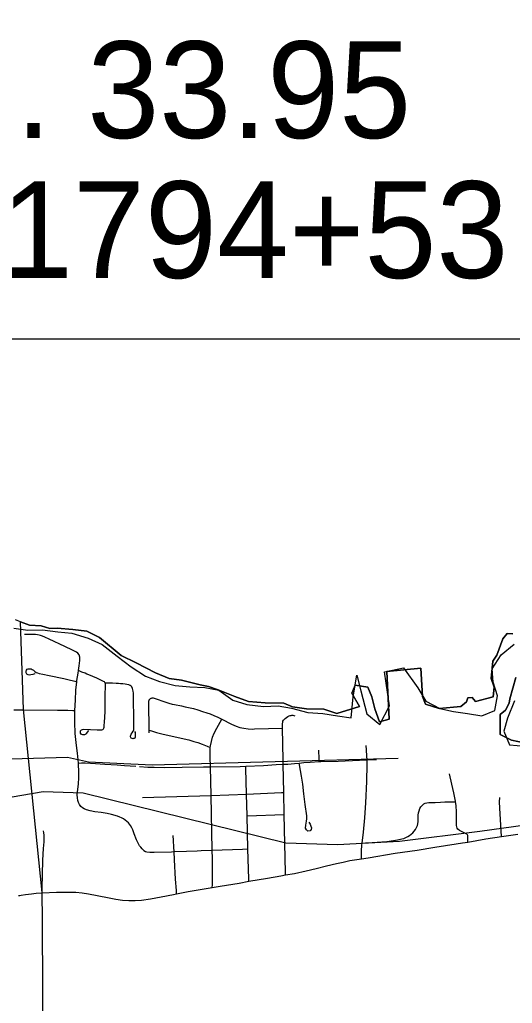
# Model space of a CAD drawing. Extents: x -12 to 34, y 0 to 22.
# Drawn here: x 7.187 to 7.899, y 18.102 to 19.526 of the extents above; entities that cross this region are included whole.
import ezdxf

# ---------------------------------------------------------------- set-up
doc = ezdxf.new("R2010")
doc.units = 0
for name, color, linetype in [('GM_X_Adjacent_County', 7, 'Continuous'), ('GM_X_Airport_Location_Class_2', 7, 'Continuous'), ('GM_X_Corporation', 7, 'Continuous'), ('GM_X_Major_Lake', 7, 'Continuous'), ('GM_X_Major_River', 7, 'Continuous'), ('GM_X_Minor_River', 7, 'Continuous'), ('GM_X_State_Location', 7, 'Continuous'), ('GM_X_Township', 7, 'Continuous')]:
    doc.layers.add(name, color=color, linetype=linetype)

msp = doc.modelspace()

# ---------------------------------------------------------------- linework, layer by layer
at = {"layer": 'GM_X_Adjacent_County'}
msp.add_lwpolyline([(6.6266, 19.8024), (8.3735, 19.8024), (8.3735, 19.0635), (6.6266, 19.0635)], close=True, dxfattribs=at)
at = {"layer": 'GM_X_Airport_Location_Class_2'}
for points in [[(7.9003, 18.6372), (7.8917, 18.6377), (7.8855, 18.6297), (7.8772, 18.6063), (7.8713, 18.5977), (7.8686, 18.5722), (7.8732, 18.5601), (7.8717, 18.5459), (7.846, 18.5389), (7.8412, 18.5448), (7.8348, 18.5445), (7.8331, 18.5386), (7.8251, 18.5321), (7.7935, 18.5292), (7.7738, 18.5354), (7.7692, 18.5466), (7.7668, 18.5872), (7.7177, 18.5824), (7.7211, 18.5136), (7.7071, 18.5096), (7.7007, 18.5286), (7.6959, 18.5458), (7.6905, 18.5598), (7.6722, 18.5628), (7.6674, 18.5512), (7.6781, 18.5321), (7.6454, 18.5219), (7.6266, 18.5281), (7.6016, 18.5286), (7.5814, 18.5316), (7.5688, 18.5367), (7.5419, 18.5372), (7.5177, 18.5391), (7.4979, 18.5466), (7.4738, 18.5558), (7.46, 18.5609), (7.4476, 18.5633), (7.4208, 18.5698), (7.403, 18.5722), (7.3829, 18.5805), (7.3552, 18.595), (7.3337, 18.6058), (7.302, 18.6315), (7.284, 18.6407), (7.2633, 18.6434), (7.2408, 18.645), (7.2303, 18.6447), (7.2177, 18.6487), (7.201, 18.6498), (7.1879, 18.6546), (7.1806, 18.6573)], [(7.9003, 18.6372), (7.8917, 18.6377), (7.8855, 18.6297), (7.8772, 18.6063), (7.8713, 18.5977), (7.8686, 18.5722), (7.8732, 18.5601), (7.8717, 18.5459), (7.846, 18.5389), (7.8412, 18.5448), (7.8348, 18.5445), (7.8331, 18.5386), (7.8251, 18.5321), (7.7935, 18.5292), (7.7738, 18.5354), (7.7692, 18.5466), (7.7668, 18.5872), (7.7177, 18.5824), (7.7211, 18.5136), (7.7071, 18.5096), (7.7007, 18.5286), (7.6959, 18.5458), (7.6905, 18.5598), (7.6722, 18.5628), (7.6674, 18.5512), (7.6781, 18.5321), (7.6454, 18.5219), (7.6266, 18.5281), (7.6016, 18.5286), (7.5814, 18.5316), (7.5688, 18.5367), (7.5419, 18.5372), (7.5177, 18.5391), (7.4979, 18.5466), (7.4738, 18.5558), (7.46, 18.5609), (7.4476, 18.5633), (7.4208, 18.5698), (7.403, 18.5722), (7.3829, 18.5805), (7.3552, 18.595), (7.3337, 18.6058), (7.302, 18.6315), (7.284, 18.6407), (7.2633, 18.6434), (7.2408, 18.645), (7.2303, 18.6447), (7.2177, 18.6487), (7.201, 18.6498), (7.1879, 18.6546), (7.1806, 18.6573)], [(7.2233, 17.4111), (7.2195, 18.2227), (7.219, 18.2628), (7.192, 18.5278), (7.1879, 18.6546), (7.201, 18.6498), (7.2177, 18.6487), (7.2303, 18.6447), (7.2408, 18.645), (7.2633, 18.6434), (7.284, 18.6407), (7.302, 18.6315), (7.3337, 18.6058), (7.3552, 18.595), (7.3829, 18.5805), (7.403, 18.5722), (7.4208, 18.5698), (7.4476, 18.5633), (7.46, 18.5609), (7.4738, 18.5558), (7.4979, 18.5466), (7.5177, 18.5391), (7.5419, 18.5372), (7.5688, 18.5367), (7.5814, 18.5316), (7.6016, 18.5286), (7.6266, 18.5281), (7.6454, 18.5219), (7.6781, 18.5321), (7.6674, 18.5512), (7.6722, 18.5628), (7.6905, 18.5598), (7.6959, 18.5458), (7.7007, 18.5286), (7.7071, 18.5096), (7.7211, 18.5136), (7.7177, 18.5824), (7.7668, 18.5872), (7.7692, 18.5466), (7.7738, 18.5354), (7.7935, 18.5292), (7.8251, 18.5321), (7.8331, 18.5386), (7.8348, 18.5445), (7.8412, 18.5448), (7.846, 18.5389), (7.8717, 18.5459), (7.8732, 18.5601), (7.8686, 18.5722), (7.8713, 18.5977), (7.8772, 18.6063), (7.8855, 18.6297), (7.8917, 18.6377), (7.9003, 18.6372)], [(7.9167, 18.4795), (7.8984, 18.4832), (7.882, 18.4913), (7.8818, 18.5203), (7.8893, 18.5265), (7.8949, 18.5367), (7.8957, 18.5429), (7.9043, 18.5738)], [(7.9043, 18.5738), (7.8957, 18.5429), (7.8949, 18.5367), (7.8893, 18.5265), (7.8818, 18.5203), (7.882, 18.4913), (7.8984, 18.4832), (7.9167, 18.4795)], [(7.9167, 18.4795), (7.8984, 18.4832), (7.882, 18.4913), (7.8818, 18.5203), (7.8893, 18.5265), (7.8949, 18.5367), (7.8957, 18.5429), (7.9043, 18.5738)]]:
    msp.add_lwpolyline(points, dxfattribs=at)
at = {"layer": 'GM_X_Corporation'}
for points in [[(4.2152, 16.8961), (4.3122, 16.9647), (4.7469, 17.316), (5.0381, 17.5535), (5.1871, 17.6698), (5.6595, 18.0409), (6.0545, 18.3551), (6.0978, 18.3867), (6.1312, 18.4021), (6.1695, 18.4095), (6.5535, 18.4423), (6.6901, 18.4479), (6.8503, 18.4485), (6.9294, 18.4522), (7.1075, 18.4541), (7.2559, 18.4584), (7.2861, 18.4516), (7.3783, 18.4473), (7.7344, 18.4572)], [(5.8151, 17.1077), (6.2198, 17.2736), (6.4243, 17.354), (6.5061, 17.4016), (6.5567, 17.4596), (6.585, 17.5147), (6.6051, 17.5675), (6.6162, 17.6256), (6.62, 17.674), (6.6177, 18.0624), (6.6371, 18.1271), (6.6557, 18.1606), (6.7018, 18.1993), (6.7606, 18.2254), (7.0425, 18.3601), (7.0932, 18.3811), (7.1588, 18.3984), (7.2206, 18.4089), (7.2787, 18.4071), (7.5718, 18.3347), (7.6466, 18.3322), (7.7363, 18.3372), (7.8525, 18.3514), (8.033, 18.3768)]]:
    msp.add_lwpolyline(points, dxfattribs=at)
at = {"layer": 'GM_X_Major_Lake'}
for points in [[(7.4653, 18.2699), (7.4766, 18.2718), (7.5042, 18.2765), (7.5181, 18.279), (7.5453, 18.2837), (7.5644, 18.2871), (7.5714, 18.2883), (7.5843, 18.2905), (7.6011, 18.294), (7.6156, 18.2974), (7.6307, 18.3012), (7.6448, 18.3047), (7.6545, 18.3069), (7.6645, 18.3089), (7.6814, 18.3116), (7.6909, 18.3131), (7.7298, 18.3196), (7.7617, 18.324), (7.7875, 18.3282), (7.8182, 18.333), (7.8273, 18.3346), (7.8352, 18.3358), (7.8613, 18.3403), (7.8838, 18.3438), (7.9073, 18.3473)], [(7.1851, 18.2582), (7.1868, 18.2585), (7.1889, 18.2589), (7.195, 18.2599), (7.2035, 18.2609)], [(7.2035, 18.2609), (7.2105, 18.2616), (7.2192, 18.2622), (7.2399, 18.2633), (7.2554, 18.2635), (7.2678, 18.2631), (7.277, 18.2623), (7.2862, 18.261), (7.3136, 18.2554), (7.3259, 18.2533), (7.3352, 18.2517), (7.3445, 18.251), (7.3538, 18.251), (7.3629, 18.2519), (7.3757, 18.2538), (7.3911, 18.2563), (7.4093, 18.2599), (7.4137, 18.2608), (7.4306, 18.264), (7.4653, 18.2699)]]:
    msp.add_lwpolyline(points, dxfattribs=at)
at = {"layer": 'GM_X_Major_River'}
msp.add_line((7.1783, 18.5271), (7.1922, 18.5272), dxfattribs=at)
at = {"layer": 'GM_X_Minor_River'}
for points in [[(7.1781, 18.645), (7.1986, 18.6423), (7.2196, 18.6427), (7.242, 18.6397), (7.2621, 18.6382), (7.2857, 18.6309), (7.3059, 18.6214), (7.3279, 18.6047), (7.3477, 18.5895), (7.3686, 18.5758), (7.3888, 18.5679), (7.4116, 18.5622), (7.4329, 18.5603), (7.4546, 18.5595), (7.4747, 18.5557), (7.4949, 18.5413), (7.5154, 18.5348), (7.5394, 18.5318), (7.5606, 18.5329), (7.58, 18.5295), (7.6036, 18.5234), (7.6253, 18.5219), (7.6466, 18.5185), (7.666, 18.5155), (7.669, 18.5459), (7.6743, 18.5774), (7.6804, 18.5546), (7.6888, 18.5215), (7.7078, 18.506), (7.7215, 18.5329), (7.7146, 18.582), (7.742, 18.588), (7.7629, 18.5588), (7.7743, 18.5394), (7.7945, 18.5292), (7.8143, 18.5246), (7.8344, 18.5216), (7.8553, 18.5185), (7.8743, 18.5261), (7.8781, 18.5474), (7.8717, 18.5672), (7.8701, 18.5865), (7.8831, 18.6067), (7.9021, 18.6223)], [(7.1781, 18.645), (7.1986, 18.6423), (7.2196, 18.6427), (7.242, 18.6397), (7.2621, 18.6382), (7.2857, 18.6309), (7.3059, 18.6214), (7.3279, 18.6047), (7.3477, 18.5895), (7.3686, 18.5758), (7.3888, 18.5679), (7.4116, 18.5622), (7.4329, 18.5603), (7.4546, 18.5595), (7.4747, 18.5557), (7.4949, 18.5413), (7.5154, 18.5348), (7.5394, 18.5318), (7.5606, 18.5329), (7.58, 18.5295), (7.6036, 18.5234), (7.6253, 18.5219), (7.6466, 18.5185), (7.666, 18.5155), (7.669, 18.5459), (7.6743, 18.5774), (7.6804, 18.5546), (7.6888, 18.5215), (7.7078, 18.506), (7.7215, 18.5329), (7.7146, 18.582), (7.742, 18.588), (7.7629, 18.5588), (7.7743, 18.5394), (7.7945, 18.5292), (7.8143, 18.5246), (7.8344, 18.5216), (7.8553, 18.5185), (7.8743, 18.5261), (7.8781, 18.5474), (7.8717, 18.5672), (7.8701, 18.5865), (7.8831, 18.6067), (7.9021, 18.6223)], [(7.9025, 18.5402), (7.8926, 18.5151), (7.8869, 18.4961), (7.8953, 18.4763), (7.9173, 18.4745)], [(7.9025, 18.5402), (7.8926, 18.5151), (7.8869, 18.4961), (7.8953, 18.4763), (7.9173, 18.4745)]]:
    msp.add_lwpolyline(points, dxfattribs=at)
at = {"layer": 'GM_X_State_Location'}
msp.add_line((7.5157, 18.3738), (7.5695, 18.3755), dxfattribs=at)
for points in [[(7.3665, 18.3234), (7.3639, 18.3259), (7.3618, 18.3283), (7.3599, 18.3305), (7.3585, 18.333), (7.3569, 18.3363), (7.3556, 18.3392), (7.3525, 18.3477), (7.3513, 18.3507), (7.3503, 18.3535), (7.349, 18.3564), (7.3471, 18.3597), (7.3456, 18.3618), (7.3439, 18.3637), (7.3417, 18.3657), (7.3393, 18.3676), (7.3367, 18.3692), (7.334, 18.3707), (7.3313, 18.3719), (7.3284, 18.373), (7.3195, 18.3756), (7.3131, 18.377), (7.3046, 18.3784), (7.2956, 18.3797), (7.2885, 18.381), (7.2834, 18.3824), (7.2801, 18.3839), (7.2777, 18.3853), (7.2753, 18.3873), (7.2731, 18.3903), (7.2715, 18.3932), (7.2707, 18.3961), (7.2702, 18.3996), (7.27, 18.4043), (7.2715, 18.4199), (7.2723, 18.4288), (7.2723, 18.4376), (7.2716, 18.4487), (7.2715, 18.4498), (7.2701, 18.4642), (7.2689, 18.4754), (7.2671, 18.4927), (7.2663, 18.5092), (7.2665, 18.5249), (7.2665, 18.526), (7.2673, 18.5412), (7.2681, 18.5555), (7.2693, 18.5676), (7.2695, 18.5694), (7.2711, 18.58), (7.2716, 18.5838), (7.2725, 18.5907), (7.2735, 18.5983), (7.2739, 18.6035), (7.2729, 18.6068), (7.271, 18.6089), (7.2687, 18.6106), (7.2632, 18.6133), (7.2518, 18.6186), (7.2293, 18.6292), (7.2231, 18.632), (7.2195, 18.6336), (7.2169, 18.6346), (7.2147, 18.6353), (7.2124, 18.6358), (7.2096, 18.6361), (7.206, 18.6362), (7.1998, 18.6362), (7.1938, 18.6359)], [(7.2088, 18.5792), (7.2055, 18.578), (7.203, 18.5775), (7.2007, 18.5774), (7.199, 18.5777), (7.1979, 18.5781), (7.1971, 18.5788), (7.1964, 18.5797), (7.1961, 18.5807), (7.196, 18.5819), (7.196, 18.583), (7.1965, 18.5846), (7.1975, 18.5858), (7.1987, 18.5863), (7.2002, 18.5866), (7.2018, 18.5865), (7.2034, 18.5862), (7.2047, 18.5855), (7.2064, 18.5843), (7.2085, 18.5826), (7.2105, 18.5813), (7.2125, 18.5804), (7.2147, 18.5797), (7.22, 18.5787), (7.2292, 18.5769), (7.2505, 18.5723), (7.2565, 18.5709), (7.2663, 18.5684), (7.2693, 18.5676)], [(7.2863, 18.4973), (7.283, 18.4929), (7.2822, 18.492), (7.2815, 18.4913), (7.2805, 18.4909), (7.2793, 18.4907), (7.278, 18.4908), (7.2765, 18.4912), (7.2756, 18.4918), (7.2748, 18.4931), (7.2745, 18.4942), (7.2745, 18.4952), (7.2748, 18.4965), (7.2753, 18.4974), (7.2763, 18.4983), (7.2777, 18.4987), (7.2795, 18.499), (7.2988, 18.498), (7.3041, 18.498), (7.3057, 18.4981), (7.3068, 18.4985), (7.3075, 18.4989), (7.3081, 18.4996), (7.3085, 18.5004), (7.3088, 18.5019), (7.3091, 18.5047), (7.3094, 18.5088), (7.3101, 18.5245), (7.3105, 18.5472), (7.311, 18.5626), (7.3109, 18.5639), (7.3107, 18.5649), (7.3104, 18.5657), (7.3098, 18.5668), (7.3092, 18.5675), (7.308, 18.5681), (7.2982, 18.5728), (7.2924, 18.5752), (7.2867, 18.5775), (7.284, 18.5787), (7.2814, 18.5799), (7.2765, 18.5818), (7.2716, 18.5838)], [(7.3528, 18.4958), (7.3535, 18.4942), (7.3538, 18.4925), (7.3539, 18.4909), (7.3539, 18.4894), (7.3539, 18.4882), (7.3536, 18.4872), (7.3534, 18.4866), (7.353, 18.486), (7.3524, 18.4856), (7.3515, 18.4855), (7.3506, 18.4853), (7.3492, 18.4856), (7.3481, 18.4861), (7.3475, 18.4869), (7.3472, 18.488), (7.3472, 18.4892), (7.3475, 18.4904), (7.348, 18.4917), (7.3495, 18.494), (7.351, 18.496), (7.3514, 18.4969), (7.3518, 18.498), (7.3519, 18.4993), (7.352, 18.5047), (7.3519, 18.5111), (7.3516, 18.5206), (7.3515, 18.5361), (7.3514, 18.5435), (7.3514, 18.5477), (7.3513, 18.5513), (7.351, 18.5542), (7.3505, 18.5561), (7.3499, 18.5579), (7.3487, 18.5602), (7.3477, 18.5612), (7.3463, 18.5623), (7.3446, 18.5632), (7.3419, 18.5639), (7.3391, 18.5642), (7.336, 18.5645), (7.3326, 18.5648), (7.3297, 18.565), (7.3261, 18.5652), (7.3208, 18.5655), (7.3139, 18.5657), (7.3104, 18.5657)], [(7.3741, 18.4938), (7.374, 18.4976), (7.3734, 18.5377), (7.3736, 18.5392), (7.3737, 18.5401), (7.3739, 18.5408), (7.3742, 18.5414), (7.3745, 18.542), (7.375, 18.5426), (7.3755, 18.5431), (7.376, 18.5435), (7.3767, 18.5438), (7.3773, 18.544), (7.3781, 18.5442), (7.3796, 18.5442), (7.3812, 18.5439), (7.3842, 18.543), (7.3954, 18.539), (7.4025, 18.5367), (7.4071, 18.5354), (7.4106, 18.5347), (7.4209, 18.5327), (7.426, 18.5316), (7.4381, 18.5289), (7.4444, 18.527), (7.4509, 18.5249), (7.4574, 18.5229), (7.4621, 18.5213), (7.4675, 18.5191), (7.4731, 18.5164), (7.4791, 18.5135), (7.493, 18.5063), (7.4997, 18.5035), (7.5052, 18.5017), (7.5109, 18.5004), (7.5171, 18.4997), (7.5233, 18.4993), (7.5266, 18.4994), (7.5667, 18.5004), (7.5669, 18.5049), (7.567, 18.5068), (7.5673, 18.5091), (7.5676, 18.5107), (7.5683, 18.512), (7.5692, 18.5131), (7.5705, 18.5143), (7.5728, 18.516), (7.5747, 18.5172), (7.5766, 18.5182), (7.5779, 18.5187), (7.5794, 18.5191), (7.5806, 18.5192), (7.5817, 18.5192), (7.5831, 18.519), (7.5845, 18.5184)], [(7.1922, 18.5272), (7.2414, 18.5266), (7.2564, 18.5264), (7.2633, 18.5261), (7.2665, 18.526)], [(7.4653, 18.2699), (7.4654, 18.2737), (7.4658, 18.2923), (7.4655, 18.312), (7.4653, 18.3241), (7.4636, 18.4031), (7.4625, 18.4447), (7.4621, 18.4587), (7.4621, 18.4679), (7.4624, 18.4725), (7.4628, 18.475), (7.4641, 18.4812), (7.4658, 18.4875), (7.468, 18.4931), (7.4718, 18.5006), (7.4767, 18.5093), (7.4791, 18.5135)], [(7.374, 18.4976), (7.3787, 18.496), (7.3846, 18.4943), (7.3944, 18.4921), (7.4313, 18.4835), (7.4387, 18.4815), (7.4444, 18.4796), (7.4507, 18.4772), (7.4577, 18.4745), (7.4624, 18.4725)], [(7.5714, 18.2883), (7.5713, 18.2919), (7.5695, 18.3755), (7.5688, 18.4075), (7.5679, 18.4483), (7.5677, 18.4546), (7.5667, 18.5004)], [(7.6814, 18.3116), (7.6814, 18.3158), (7.6814, 18.3231), (7.6817, 18.3314), (7.6821, 18.334), (7.6841, 18.3501), (7.6861, 18.3707), (7.6875, 18.3926), (7.6889, 18.4232), (7.6893, 18.4479), (7.6892, 18.4545), (7.6891, 18.4602), (7.6885, 18.4694), (7.6879, 18.4756)], [(7.6201, 18.4521), (7.6199, 18.4557), (7.6197, 18.4605), (7.6196, 18.4643), (7.6194, 18.4688)], [(7.2715, 18.4498), (7.2763, 18.4503), (7.2816, 18.4503), (7.2961, 18.4495), (7.3099, 18.4485), (7.3278, 18.4474), (7.3382, 18.4466), (7.3548, 18.4454)], [(7.36, 18.445), (7.3719, 18.4443), (7.3812, 18.444), (7.3967, 18.4437), (7.4216, 18.4439), (7.4526, 18.4445), (7.4625, 18.4447), (7.5057, 18.4453), (7.5137, 18.4457), (7.5394, 18.4467), (7.5579, 18.4478), (7.5679, 18.4483), (7.5747, 18.4486), (7.5844, 18.4494), (7.5911, 18.4501), (7.5979, 18.4508), (7.6071, 18.4514), (7.6201, 18.4521), (7.6225, 18.4522), (7.6474, 18.4528), (7.6784, 18.4541), (7.6892, 18.4545), (7.703, 18.455)], [(7.5181, 18.279), (7.518, 18.282), (7.5169, 18.3261), (7.5157, 18.3738), (7.5149, 18.405), (7.5138, 18.4424), (7.5137, 18.4457)], [(7.605, 18.3644), (7.6067, 18.3617), (7.608, 18.3589), (7.6088, 18.3564), (7.6085, 18.3537), (7.6067, 18.3519), (7.6037, 18.3517), (7.6014, 18.3533), (7.6003, 18.3559), (7.6006, 18.3604), (7.6018, 18.3662), (7.602, 18.3693), (7.6019, 18.3736), (7.5998, 18.3902), (7.5979, 18.4055), (7.5961, 18.4196), (7.5946, 18.431), (7.5916, 18.4476), (7.5911, 18.4501)], [(7.8174, 18.3939), (7.8173, 18.3947), (7.8149, 18.4071), (7.812, 18.4193), (7.8084, 18.4346)], [(7.3645, 18.4001), (7.4636, 18.4031), (7.5149, 18.405), (7.5653, 18.4073), (7.5688, 18.4075)], [(7.6821, 18.334), (7.6871, 18.3345), (7.6966, 18.3353), (7.718, 18.3368), (7.7273, 18.3378), (7.7334, 18.3388), (7.7395, 18.3402), (7.7425, 18.3411), (7.7454, 18.3423), (7.7482, 18.3436), (7.7508, 18.3452), (7.7532, 18.3471), (7.7555, 18.3492), (7.7575, 18.3516), (7.7593, 18.3541), (7.7608, 18.3568), (7.7621, 18.3597), (7.7628, 18.3623), (7.7631, 18.3657), (7.7631, 18.37), (7.7634, 18.3749), (7.7638, 18.3781), (7.7645, 18.3811), (7.7657, 18.3842), (7.767, 18.3865), (7.7692, 18.3891), (7.7714, 18.391), (7.7734, 18.3918), (7.7758, 18.3925), (7.7786, 18.3928), (7.7824, 18.393), (7.7876, 18.3931), (7.7955, 18.3936), (7.8017, 18.3938), (7.8072, 18.3941), (7.8139, 18.3939), (7.8174, 18.3939)], [(7.8352, 18.3358), (7.8352, 18.3389), (7.8352, 18.3432), (7.8352, 18.344), (7.8351, 18.3452), (7.8347, 18.3462), (7.8337, 18.3471), (7.8317, 18.348), (7.8259, 18.351), (7.8231, 18.3525), (7.8207, 18.3544), (7.8197, 18.3558), (7.819, 18.3576), (7.8187, 18.3596), (7.8187, 18.3621), (7.8187, 18.3665), (7.8188, 18.3791), (7.8181, 18.3885), (7.8174, 18.3939)], [(7.8838, 18.3438), (7.8832, 18.3519), (7.8813, 18.385), (7.8809, 18.394), (7.8811, 18.4001)], [(7.2192, 18.2622), (7.2194, 18.2691), (7.2197, 18.2887), (7.2201, 18.3097), (7.2211, 18.3265), (7.2219, 18.3362), (7.2221, 18.3409), (7.222, 18.3458), (7.2216, 18.3491), (7.2211, 18.352)], [(7.4137, 18.2608), (7.4134, 18.2656), (7.4122, 18.2823), (7.4108, 18.3099), (7.41, 18.3219), (7.4097, 18.3284), (7.409, 18.3382), (7.4085, 18.3454)], [(7.3665, 18.3234), (7.3687, 18.3222), (7.3707, 18.3216), (7.3747, 18.3213), (7.381, 18.3212), (7.4061, 18.3218), (7.41, 18.3219), (7.4279, 18.3226), (7.4432, 18.3232), (7.4493, 18.3234), (7.4653, 18.3241), (7.5088, 18.3257), (7.5169, 18.3261)]]:
    msp.add_lwpolyline(points, dxfattribs=at)
at = {"layer": 'GM_X_Township'}
for points in [[(7.4653, 18.2699), (7.4766, 18.2718), (7.5042, 18.2765), (7.5181, 18.279), (7.5453, 18.2837), (7.5644, 18.2871), (7.5714, 18.2883), (7.5843, 18.2905), (7.6011, 18.294), (7.6156, 18.2974), (7.6307, 18.3012), (7.6448, 18.3047), (7.6545, 18.3069), (7.6645, 18.3089), (7.6814, 18.3116), (7.6909, 18.3131), (7.7298, 18.3196), (7.7617, 18.324), (7.7875, 18.3282), (7.8182, 18.333), (7.8273, 18.3346), (7.8352, 18.3358), (7.8613, 18.3403), (7.8838, 18.3438), (7.9073, 18.3473)], [(7.1851, 18.2582), (7.1868, 18.2585), (7.1889, 18.2589), (7.195, 18.2599), (7.2035, 18.2609)], [(7.2035, 18.2609), (7.2105, 18.2616), (7.2192, 18.2622), (7.2399, 18.2633), (7.2554, 18.2635), (7.2678, 18.2631), (7.277, 18.2623), (7.2862, 18.261), (7.3136, 18.2554), (7.3259, 18.2533), (7.3352, 18.2517), (7.3445, 18.251), (7.3538, 18.251), (7.3629, 18.2519), (7.3757, 18.2538), (7.3911, 18.2563), (7.4093, 18.2599), (7.4137, 18.2608), (7.4306, 18.264), (7.4653, 18.2699)]]:
    msp.add_lwpolyline(points, dxfattribs=at)

# ---------------------------------------------------------------- texts
at = {"layer": 'GM_X_Adjacent_County'}
for s, p in [('S.L.M. 33.95', (6.6915, 19.3544)), ('STA. 1794+53', (6.6915, 19.1519))]:
    msp.add_text(s, height=0.14, dxfattribs=at).set_placement(p)

doc.saveas('drawing.dxf')
